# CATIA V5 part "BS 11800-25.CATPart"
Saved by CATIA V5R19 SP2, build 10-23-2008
Part number: BS 11800-25
Bounding box of the stored display mesh (mm): x -74.81 to 74.81, y -74.81 to 74.81, z 0 to 128
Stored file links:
  C:\Users\Bora\Desktop\3D Katı model\BS serisi\BS 11800\BS 11800-25.CATPart
  C:\Program Files\Dassault Systemes\B19\intel_a\reffiles\standard\MetricThickPitch.txt
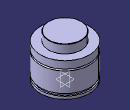
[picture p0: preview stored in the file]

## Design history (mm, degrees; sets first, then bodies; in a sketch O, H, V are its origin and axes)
Body1 (main body)
  Sketch1 on yz-plane, origin (0, 0, 0), H (0, 1, 0), V (0, 0, 1)
    point P1 (75, 80)
    point P2 (75, 75)
    point P5 (50, 127)
    point P7 (50, 127)
    point P12 (75, 75)
    point P13 (75, 80)
    arc A1 centre (75, 77.5) radius 2.5 from (75, 80) to (75, 75) ccw
    line L1 (75, 0) -> (75, 8)
    line L2 (50, 127) -> (50, 102)
    arc A2 centre (49, 127) radius 1 from (50, 127) to (49, 128) ccw
    line L3 (71, 15) -> (71, 8)
    line L4 (75, 15) -> (75, 75)
    line L5 (75, 80) -> (75, 102)
    line L6 (49, 128) -> (0, 128)
    point P15 (0, 128)
    line L7 (50, 102) -> (75, 102)
    line L8 (0, 0) -> (75, 0)
    line L9 (71, 15) -> (75, 15)
    line L10 (71, 8) -> (75, 8)
    coincidence: P15 V, P1 P13, P2 P12, P5 P7
    tangency: L6 A2
    horizontal: L7 H, L8 H, L9 H, L10 H
  Shaft1: profile Sketch1, axis Sketch1.V, angle 360
  Sketch2 on face of Shaft1 from Sketch1.L8, origin (0, 0, 0), H (1, 0, 0), V (0, -1, 0)
    point P1 (50, 0)
    distance P1 V = 50
  Hole1: placed by Sketch2, at (50, 0, 0) direction (0, 0, 1), diameter 8.376, depth 12, threaded "M10", thread diameter 10, thread depth 12, pitch 1.5
  CircPattern1: of Hole1, instances 4, angular step 90, axis from xy-plane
